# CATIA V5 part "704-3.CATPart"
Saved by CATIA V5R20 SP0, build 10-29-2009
Part number: 704-3
Revision: TUTTO
Definition: NON CONOSCIUTO
Nomenclature: 704-3
Source: Unknown
Bounding box of the stored display mesh (mm): x -45 to 10, y -10 to 10, z 0 to 90
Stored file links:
  C:\Users\Utente\Desktop\IO LAVORO\3D X SITO CF\X SITO\704\704-3.CATPart
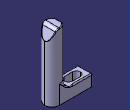
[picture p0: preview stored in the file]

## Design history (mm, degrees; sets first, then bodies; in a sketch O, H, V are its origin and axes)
Body1 "Importato1" (main body)
  Solid1: solid without history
